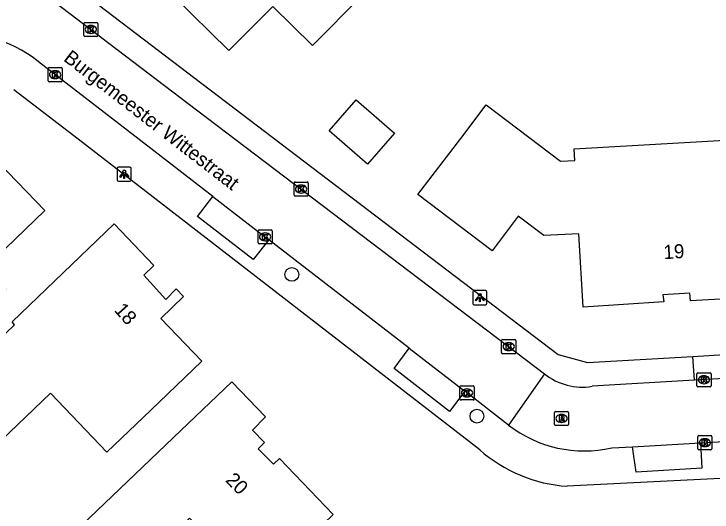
# Model space of a CAD drawing. Extents: x 159503 to 160347, y 382525 to 383272.
# Drawn here: x 159934.24 to 159983.69, y 382951.53 to 382986.8 of the extents above; entities that cross this region are included whole.
import ezdxf

# ---------------------------------------------------------------- set-up
doc = ezdxf.new("R2010")
doc.units = 0
for name, color, linetype in [('IMGEO_Boom', 7, 'Continuous'), ('IMGEO_Kolk', 7, 'Continuous'), ('IMGEO_Lichtpunt', 7, 'Continuous'), ('IMGEO_Openbare_ruimte_label', 7, 'Continuous'), ('IMGEO_Pand', 7, 'Continuous'), ('IMGEO_Pand_nummerreeks', 7, 'Continuous'), ('IMGEO_Rijbaan_lokaal_open', 7, 'Continuous'), ('IMGEO_Rioolput', 7, 'Continuous'), ('IMGEO_Voetpad_open', 7, 'Continuous')]:
    doc.layers.add(name, color=color, linetype=linetype)

msp = doc.modelspace()

# ---------------------------------------------------------------- linework, layer by layer
at = {"layer": 'IMGEO_Boom'}
for centre in [(159953.927, 382968.359), (159967.036, 382958.322)]:
    msp.add_circle(centre, 0.489, dxfattribs=at)
at = {"layer": 'IMGEO_Kolk'}
for p, q in [((159939.189, 382985.279), (159939.189, 382986.131)), ((159939.264, 382986.205), (159940.116, 382986.205)), ((159940.19, 382986.131), (159940.19, 382985.279)), ((159939.677, 382985.985), (159939.702, 382985.985)), ((159940.116, 382985.205), (159939.264, 382985.205)), ((159939.7, 382985.425), (159939.675, 382985.425)), ((159936.656, 382982.077), (159936.656, 382982.929)), ((159936.731, 382983.003), (159937.583, 382983.003)), ((159937.144, 382982.783), (159937.169, 382982.783)), ((159937.657, 382982.929), (159937.657, 382982.077)), ((159937.167, 382982.223), (159937.142, 382982.223)), ((159937.583, 382982.003), (159936.731, 382982.003)), ((159954.082, 382973.977), (159954.082, 382974.829)), ((159954.157, 382974.903), (159955.009, 382974.903)), ((159954.57, 382974.683), (159954.595, 382974.683)), ((159955.083, 382974.829), (159955.083, 382973.977)), ((159955.009, 382973.903), (159954.157, 382973.903)), ((159954.593, 382974.123), (159954.568, 382974.123)), ((159951.531, 382970.593), (159951.531, 382971.445)), ((159951.606, 382971.519), (159952.458, 382971.519)), ((159952.019, 382971.299), (159952.044, 382971.299)), ((159952.532, 382971.445), (159952.532, 382970.593)), ((159952.042, 382970.739), (159952.017, 382970.739)), ((159952.458, 382970.519), (159951.606, 382970.519)), ((159968.863, 382963.746), (159969.715, 382963.746)), ((159968.788, 382962.82), (159968.788, 382963.672)), ((159969.276, 382963.526), (159969.301, 382963.526)), ((159969.789, 382963.672), (159969.789, 382962.82)), ((159969.299, 382962.966), (159969.274, 382962.966)), ((159969.715, 382962.746), (159968.863, 382962.746)), ((159982.62, 382960.473), (159982.62, 382961.325)), ((159982.695, 382961.399), (159983.547, 382961.399)), ((159983.621, 382961.325), (159983.621, 382960.473)), ((159983.108, 382961.179), (159983.133, 382961.179)), ((159965.834, 382959.54), (159965.834, 382960.392)), ((159965.909, 382960.466), (159966.761, 382960.466)), ((159966.835, 382960.392), (159966.835, 382959.54)), ((159983.547, 382960.399), (159982.695, 382960.399)), ((159983.131, 382960.619), (159983.106, 382960.619)), ((159966.322, 382960.246), (159966.347, 382960.246)), ((159966.761, 382959.466), (159965.909, 382959.466)), ((159966.345, 382959.686), (159966.32, 382959.686)), ((159982.678, 382956.015), (159982.678, 382956.867)), ((159982.753, 382956.941), (159983.605, 382956.941)), ((159983.679, 382956.867), (159983.679, 382956.015)), ((159983.166, 382956.721), (159983.191, 382956.721)), ((159983.605, 382955.941), (159982.753, 382955.941)), ((159983.189, 382956.161), (159983.164, 382956.161))]:
    msp.add_line(p, q, dxfattribs=at)
for points in [[(159939.189, 382985.279), (159939.189, 382986.131)], [(159939.264, 382986.205), (159940.116, 382986.205)], [(159940.19, 382986.131), (159940.19, 382985.279)], [(159939.51, 382985.905), (159939.633, 382985.905), (159939.633, 382985.754), (159939.763, 382985.905), (159939.927, 382985.905), (159939.781, 382985.754), (159939.934, 382985.505), (159939.782, 382985.505), (159939.697, 382985.669), (159939.633, 382985.602), (159939.633, 382985.505), (159939.51, 382985.505), (159939.51, 382985.905)], [(159940.116, 382985.205), (159939.264, 382985.205)], [(159936.656, 382982.077), (159936.656, 382982.929)], [(159936.731, 382983.003), (159937.583, 382983.003)], [(159936.977, 382982.703), (159937.1, 382982.703), (159937.1, 382982.552), (159937.23, 382982.703), (159937.394, 382982.703), (159937.248, 382982.552), (159937.401, 382982.303), (159937.249, 382982.303), (159937.164, 382982.467), (159937.1, 382982.4), (159937.1, 382982.303), (159936.977, 382982.303), (159936.977, 382982.703)], [(159937.657, 382982.929), (159937.657, 382982.077)], [(159937.583, 382982.003), (159936.731, 382982.003)], [(159954.082, 382973.977), (159954.082, 382974.829)], [(159954.157, 382974.903), (159955.009, 382974.903)], [(159955.083, 382974.829), (159955.083, 382973.977)], [(159954.403, 382974.603), (159954.526, 382974.603), (159954.526, 382974.452), (159954.656, 382974.603), (159954.82, 382974.603), (159954.674, 382974.452), (159954.827, 382974.203), (159954.675, 382974.203), (159954.59, 382974.367), (159954.526, 382974.3), (159954.526, 382974.203), (159954.403, 382974.203), (159954.403, 382974.603)], [(159955.009, 382973.903), (159954.157, 382973.903)], [(159951.531, 382970.593), (159951.531, 382971.445)], [(159951.606, 382971.519), (159952.458, 382971.519)], [(159951.852, 382971.219), (159951.975, 382971.219), (159951.975, 382971.068), (159952.105, 382971.219), (159952.269, 382971.219), (159952.123, 382971.068), (159952.276, 382970.819), (159952.124, 382970.819), (159952.039, 382970.983), (159951.975, 382970.916), (159951.975, 382970.819), (159951.852, 382970.819), (159951.852, 382971.219)], [(159952.532, 382971.445), (159952.532, 382970.593)], [(159952.458, 382970.519), (159951.606, 382970.519)], [(159968.863, 382963.746), (159969.715, 382963.746)], [(159968.788, 382962.82), (159968.788, 382963.672)], [(159969.109, 382963.446), (159969.232, 382963.446), (159969.232, 382963.295), (159969.362, 382963.446), (159969.526, 382963.446), (159969.38, 382963.295), (159969.533, 382963.046), (159969.381, 382963.046), (159969.296, 382963.21), (159969.232, 382963.143), (159969.232, 382963.046), (159969.109, 382963.046), (159969.109, 382963.446)], [(159969.789, 382963.672), (159969.789, 382962.82)], [(159969.715, 382962.746), (159968.863, 382962.746)], [(159982.62, 382960.473), (159982.62, 382961.325)], [(159982.695, 382961.399), (159983.547, 382961.399)], [(159983.621, 382961.325), (159983.621, 382960.473)], [(159982.941, 382961.099), (159983.064, 382961.099), (159983.064, 382960.948), (159983.194, 382961.099), (159983.358, 382961.099), (159983.212, 382960.948), (159983.365, 382960.699), (159983.213, 382960.699), (159983.128, 382960.863), (159983.064, 382960.796), (159983.064, 382960.699), (159982.941, 382960.699), (159982.941, 382961.099)], [(159965.834, 382959.54), (159965.834, 382960.392)], [(159965.909, 382960.466), (159966.761, 382960.466)], [(159966.835, 382960.392), (159966.835, 382959.54)], [(159983.547, 382960.399), (159982.695, 382960.399)], [(159966.155, 382960.166), (159966.278, 382960.166), (159966.278, 382960.015), (159966.408, 382960.166), (159966.572, 382960.166), (159966.426, 382960.015), (159966.579, 382959.766), (159966.427, 382959.766), (159966.342, 382959.93), (159966.278, 382959.863), (159966.278, 382959.766), (159966.155, 382959.766), (159966.155, 382960.166)], [(159966.761, 382959.466), (159965.909, 382959.466)], [(159982.678, 382956.015), (159982.678, 382956.867)], [(159982.753, 382956.941), (159983.605, 382956.941)], [(159983.679, 382956.867), (159983.679, 382956.015)], [(159982.999, 382956.641), (159983.122, 382956.641), (159983.122, 382956.49), (159983.252, 382956.641), (159983.416, 382956.641), (159983.27, 382956.49), (159983.423, 382956.241), (159983.271, 382956.241), (159983.186, 382956.405), (159983.122, 382956.338), (159983.122, 382956.241), (159982.999, 382956.241), (159982.999, 382956.641)], [(159983.605, 382955.941), (159982.753, 382955.941)]]:
    msp.add_lwpolyline(points, dxfattribs=at)
for centre, start, end in [((159939.266, 382986.129), 91.552, 178.448), ((159939.266, 382986.129), 91.552, 178.448), ((159940.114, 382986.129), 1.552, 88.448), ((159940.114, 382986.129), 1.552, 88.448), ((159939.266, 382985.281), 181.552, 268.448), ((159939.266, 382985.281), 181.552, 268.448), ((159940.114, 382985.281), 271.552, 358.448), ((159940.114, 382985.281), 271.552, 358.448), ((159936.733, 382982.927), 91.552, 178.448), ((159936.733, 382982.927), 91.552, 178.448), ((159937.581, 382982.927), 1.552, 88.448), ((159937.581, 382982.927), 1.552, 88.448), ((159936.733, 382982.079), 181.552, 268.448), ((159936.733, 382982.079), 181.552, 268.448), ((159937.581, 382982.079), 271.552, 358.448), ((159937.581, 382982.079), 271.552, 358.448), ((159954.159, 382974.827), 91.552, 178.448), ((159954.159, 382974.827), 91.552, 178.448), ((159955.007, 382974.827), 1.552, 88.448), ((159955.007, 382974.827), 1.552, 88.448), ((159954.159, 382973.979), 181.552, 268.448), ((159954.159, 382973.979), 181.552, 268.448), ((159955.007, 382973.979), 271.552, 358.448), ((159955.007, 382973.979), 271.552, 358.448), ((159951.608, 382971.443), 91.552, 178.448), ((159951.608, 382971.443), 91.552, 178.448), ((159952.456, 382971.443), 1.552, 88.448), ((159952.456, 382971.443), 1.552, 88.448), ((159951.608, 382970.595), 181.552, 268.448), ((159951.608, 382970.595), 181.552, 268.448), ((159952.456, 382970.595), 271.552, 358.448), ((159952.456, 382970.595), 271.552, 358.448), ((159968.865, 382963.67), 91.552, 178.448), ((159968.865, 382963.67), 91.552, 178.448), ((159969.713, 382963.67), 1.552, 88.448), ((159969.713, 382963.67), 1.552, 88.448), ((159968.865, 382962.822), 181.552, 268.448), ((159968.865, 382962.822), 181.552, 268.448), ((159969.713, 382962.822), 271.552, 358.448), ((159969.713, 382962.822), 271.552, 358.448), ((159982.697, 382961.323), 91.552, 178.448), ((159982.697, 382961.323), 91.552, 178.448), ((159983.545, 382961.323), 1.552, 88.448), ((159983.545, 382961.323), 1.552, 88.448), ((159965.911, 382960.39), 91.552, 178.448), ((159965.911, 382960.39), 91.552, 178.448), ((159966.759, 382960.39), 1.552, 88.448), ((159966.759, 382960.39), 1.552, 88.448), ((159982.697, 382960.475), 181.552, 268.448), ((159982.697, 382960.475), 181.552, 268.448), ((159983.545, 382960.475), 271.552, 358.448), ((159983.545, 382960.475), 271.552, 358.448), ((159965.911, 382959.542), 181.552, 268.448), ((159965.911, 382959.542), 181.552, 268.448), ((159966.759, 382959.542), 271.552, 358.448), ((159966.759, 382959.542), 271.552, 358.448), ((159982.755, 382956.865), 91.552, 178.448), ((159982.755, 382956.865), 91.552, 178.448), ((159983.603, 382956.865), 1.552, 88.448), ((159983.603, 382956.865), 1.552, 88.448), ((159982.755, 382956.017), 181.552, 268.448), ((159982.755, 382956.017), 181.552, 268.448), ((159983.603, 382956.017), 271.552, 358.448), ((159983.603, 382956.017), 271.552, 358.448)]:
    msp.add_arc(centre, 0.0765, start, end, dxfattribs=at)
for centre, major_axis, ratio, start_param, end_param in [((159939.676, 382985.705), (-0.387, 0.002), 0.722429, 4.712389, 7.853982), ((159939.701, 382985.705), (-0.39, 0.002), 0.717154, 1.570796, 4.712389), ((159937.143, 382982.503), (-0.387, 0.002), 0.722429, 4.712389, 7.853982), ((159937.168, 382982.503), (-0.39, 0.002), 0.717154, 1.570796, 4.712389), ((159954.569, 382974.403), (-0.387, 0.002), 0.722429, 4.712389, 7.853982), ((159954.594, 382974.403), (-0.39, 0.002), 0.717154, 1.570796, 4.712389), ((159952.018, 382971.019), (-0.387, 0.002), 0.722429, 4.712389, 7.853982), ((159952.043, 382971.019), (-0.39, 0.002), 0.717154, 1.570796, 4.712389), ((159969.275, 382963.246), (-0.387, 0.002), 0.722429, 4.712389, 7.853982), ((159969.3, 382963.246), (-0.39, 0.002), 0.717154, 1.570796, 4.712389), ((159983.107, 382960.899), (-0.387, 0.002), 0.722429, 4.712389, 7.853982), ((159983.132, 382960.899), (-0.39, 0.002), 0.717154, 1.570796, 4.712389), ((159966.321, 382959.966), (-0.387, 0.002), 0.722429, 4.712389, 7.853982), ((159966.346, 382959.966), (-0.39, 0.002), 0.717154, 1.570796, 4.712389), ((159983.165, 382956.441), (-0.387, 0.002), 0.722429, 4.712389, 7.853982), ((159983.19, 382956.441), (-0.39, 0.002), 0.717154, 1.570796, 4.712389)]:
    msp.add_ellipse(centre, major_axis=major_axis, ratio=ratio, start_param=start_param, end_param=end_param, dxfattribs=at)
at = {"layer": 'IMGEO_Lichtpunt'}
for p, q in [((159941.56, 382975.859), (159941.56, 382975.052)), ((159941.56, 382975.859), (159941.56, 382975.052)), ((159942.462, 382975.954), (159941.654, 382975.954)), ((159942.462, 382975.954), (159941.654, 382975.954)), ((159942.556, 382975.052), (159942.556, 382975.859)), ((159942.556, 382975.052), (159942.556, 382975.859)), ((159941.654, 382974.958), (159942.462, 382974.958)), ((159941.654, 382974.958), (159942.462, 382974.958)), ((159967.644, 382967.21), (159966.836, 382967.21)), ((159967.644, 382967.21), (159966.836, 382967.21)), ((159966.742, 382967.115), (159966.742, 382966.308)), ((159966.742, 382967.115), (159966.742, 382966.308)), ((159967.738, 382966.308), (159967.738, 382967.115)), ((159967.738, 382966.308), (159967.738, 382967.115)), ((159966.836, 382966.214), (159967.644, 382966.214)), ((159966.836, 382966.214), (159967.644, 382966.214))]:
    msp.add_line(p, q, dxfattribs=at)
for points in [[(159941.934, 382975.523), (159941.973, 382975.495), (159941.785, 382975.233), (159941.747, 382975.26), (159941.934, 382975.523)], [(159942.036, 382975.475), (159942.083, 382975.475), (159942.083, 382975.153), (159942.036, 382975.153), (159942.036, 382975.475)], [(159942.146, 382975.495), (159942.184, 382975.522), (159942.371, 382975.26), (159942.332, 382975.232), (159942.146, 382975.495)], [(159967.116, 382966.779), (159967.155, 382966.751), (159966.967, 382966.489), (159966.929, 382966.516), (159967.116, 382966.779)], [(159967.218, 382966.731), (159967.265, 382966.731), (159967.265, 382966.409), (159967.218, 382966.409), (159967.218, 382966.731)], [(159967.328, 382966.751), (159967.366, 382966.778), (159967.553, 382966.516), (159967.514, 382966.488), (159967.328, 382966.751)]]:
    msp.add_lwpolyline(points, dxfattribs=at)
for centre in [(159942.059, 382975.657), (159967.241, 382966.913)]:
    msp.add_circle(centre, 0.0994, dxfattribs=at)
for centre, start, end in [((159941.654, 382975.859), 90, 180), ((159941.654, 382975.859), 90, 180), ((159942.462, 382975.859), 0, 90), ((159942.462, 382975.859), 0, 90), ((159941.654, 382975.052), 180, 270), ((159941.654, 382975.052), 180, 270), ((159942.462, 382975.052), 270, 0), ((159942.462, 382975.052), 270, 360), ((159966.836, 382967.115), 90, 180), ((159966.836, 382967.115), 90, 180), ((159967.644, 382967.115), 0, 90), ((159967.644, 382967.115), 0, 90), ((159966.836, 382966.308), 180, 270), ((159966.836, 382966.308), 180, 270), ((159967.644, 382966.308), 270, 0), ((159967.644, 382966.308), 270, 360)]:
    msp.add_arc(centre, 0.0946, start, end, dxfattribs=at)
at = {"layer": 'IMGEO_Pand'}
for points in [[(159961.16, 382990.415), (159958.888, 382988.116), (159955.382, 382984.566), (159952.57, 382987.322), (159949.454, 382984.218), (159941.58, 382991.973), (159947.894, 382998.384), (159951.029, 382995.297), (159953.143, 382993.216), (159955.69, 382995.802), (159959.253, 382992.294), (159961.16, 382990.415)], [(159961.208, 382978.373), (159959.289, 382976.161), (159956.574, 382978.516), (159958.493, 382980.728), (159961.208, 382978.373)], [(159987.908, 382978.054), (159988.265, 382971.829), (159988.551, 382966.837), (159982.16, 382966.482), (159982.117, 382967.02), (159980.216, 382966.903), (159980.265, 382966.415), (159974.571, 382966.048), (159974.248, 382971.235), (159971.787, 382971.11), (159969.948, 382972.492), (159968.113, 382970.035), (159962.862, 382974.012), (159965.887, 382977.994), (159967.689, 382980.367), (159972.945, 382976.375), (159973.964, 382976.433), (159973.916, 382977.252), (159987.908, 382978.054)], [(159916.211, 382960.394), (159919.327, 382963.349), (159920.208, 382962.421), (159923.869, 382965.893), (159920.764, 382969.094), (159920.247, 382968.592), (159917.253, 382971.679), (159918.389, 382972.78), (159914.883, 382976.395), (159916.389, 382977.855), (159919.894, 382974.24), (159923.132, 382977.38), (159924.656, 382975.807), (159925.603, 382976.725), (159926.856, 382975.432), (159930.517, 382978.982), (159936.424, 382972.89), (159932.235, 382968.858), (159933.664, 382967.34), (159930.234, 382964.041)], [(159930.234, 382964.041), (159931.771, 382962.416), (159934.286, 382964.793), (159934.106, 382964.998), (159941.347, 382971.931), (159944.155, 382968.989), (159943.448, 382968.307), (159944.994, 382966.583), (159945.743, 382967.327), (159946.261, 382966.792), (159944.645, 382965.232), (159947.554, 382962.207), (159943.937, 382958.756), (159940.81, 382955.771), (159936.827, 382959.946), (159932.161, 382955.493), (159926.984, 382960.92)], [(159942.81, 382945.14), (159941.604, 382946.347), (159935.384, 382940.398), (159932.01, 382943.902), (159946.063, 382957.311), (159949.681, 382960.761), (159952.057, 382958.267), (159951.15, 382957.329), (159951.983, 382956.452), (159951.534, 382956.005), (159952.617, 382954.913), (159953.046, 382955.323), (159956.844, 382951.362), (159953.255, 382947.882), (159951.397, 382946.081), (159946.683, 382951.101), (159944.62, 382949.165), (159945.781, 382947.93), (159942.81, 382945.14)]]:
    msp.add_lwpolyline(points, dxfattribs=at)
at = {"layer": 'IMGEO_Rijbaan_lokaal_open'}
for points in [[(159936.514, 382988.127), (159946.588, 382980.466), (159971.819, 382961.325)], [(159948.338, 382973.876), (159943.932, 382977.28), (159935.974, 382983.418)], [(159967.231, 382955.939), (159938.787, 382977.935), (159934.243, 382981.423)], [(159952.293, 382970.819), (159951.192, 382969.404), (159947.245, 382972.454), (159948.338, 382973.876)], [(159948.338, 382973.876), (159952.293, 382970.819)], [(159962.244, 382963.13), (159952.293, 382970.819)], [(159966.186, 382960.084), (159965.084, 382958.658), (159961.175, 382961.695), (159962.244, 382963.13)], [(159962.244, 382963.13), (159966.186, 382960.084)], [(159971.819, 382961.325), (159969.281, 382957.692)], [(159992.466, 382961.44), (159989.696, 382961.282), (159982.453, 382960.859)], [(159982.453, 382960.859), (159975.211, 382960.437)], [(159969.281, 382957.692), (159966.186, 382960.084)], [(159982.87, 382956.422), (159992.548, 382956.964)], [(159978.059, 382956.156), (159982.87, 382956.422)], [(159982.87, 382956.422), (159982.969, 382954.641), (159978.306, 382954.358), (159978.059, 382956.156)], [(159976.584, 382956.075), (159978.059, 382956.156)], [(160000.149, 382954.763), (159999.933, 382954.745), (159991.369, 382954.262), (159973.432, 382953.353)]]:
    msp.add_lwpolyline(points, dxfattribs=at)
for centre, radius, start, end in [((159930.645, 382976.933), 8.394, 50.5908, 102.6717), ((159974.502, 382964.651), 4.273, 231.1078, 279.5514), ((159974.645, 382964.619), 8.761, 232.245, 282.7855), ((159974.163, 382963.833), 10.506, 228.7136, 266.0112)]:
    msp.add_arc(centre, radius, start, end, dxfattribs=at)
at = {"layer": 'IMGEO_Rioolput'}
for p, q in [((159972.531, 382957.733), (159972.531, 382958.585)), ((159972.606, 382958.659), (159973.458, 382958.659)), ((159973.019, 382958.439), (159973.044, 382958.439)), ((159973.532, 382958.585), (159973.532, 382957.733)), ((159973.042, 382957.879), (159973.017, 382957.879)), ((159973.458, 382957.659), (159972.606, 382957.659))]:
    msp.add_line(p, q, dxfattribs=at)
for points in [[(159972.531, 382957.733), (159972.531, 382958.585)], [(159972.606, 382958.659), (159973.458, 382958.659)], [(159973.12, 382958.357), (159972.868, 382958.359), (159972.868, 382957.959)], [(159973.532, 382958.585), (159973.532, 382957.733)], [(159972.868, 382957.959), (159972.992, 382957.959), (159972.992, 382958.121), (159973.003, 382958.121)], [(159973.046, 382958.278), (159972.992, 382958.278), (159972.992, 382958.197)], [(159972.992, 382958.197), (159973.044, 382958.197)], [(159973.05, 382958.092), (159973.121, 382957.959), (159973.261, 382957.959), (159973.196, 382958.085)], [(159973.458, 382957.659), (159972.606, 382957.659)]]:
    msp.add_lwpolyline(points, dxfattribs=at)
for centre, radius, start, end in [((159972.608, 382958.583), 0.0765, 91.552, 178.448), ((159972.608, 382958.583), 0.0765, 91.552, 178.448), ((159973.119, 382958.247), 0.109, 350.3612, 89.416), ((159973.456, 382958.583), 0.0765, 1.552, 88.448), ((159973.456, 382958.583), 0.0765, 1.552, 88.448), ((159973.002, 382958.068), 0.0533, 26.0293, 88.6989), ((159973.028, 382958.386), 0.19, 274.7715, 282.9687), ((159973.052, 382958.182), 0.0964, 77.0061, 93.1865), ((159973.066, 382958.239), 0.0378, 276.6634, 79.6772), ((159973.117, 382958.247), 0.112, 277.5842, 350.9817), ((159973.101, 382958.032), 0.108, 29.5134, 73.7905), ((159972.608, 382957.735), 0.0765, 181.552, 268.448), ((159972.608, 382957.735), 0.0765, 181.552, 268.448), ((159973.456, 382957.735), 0.0765, 271.552, 358.448), ((159973.456, 382957.735), 0.0765, 271.552, 358.448)]:
    msp.add_arc(centre, radius, start, end, dxfattribs=at)
for centre, major_axis, ratio, start_param, end_param in [((159973.018, 382958.159), (-0.387, 0.002), 0.722429, 4.712389, 7.853982), ((159973.043, 382958.159), (-0.39, 0.002), 0.717154, 1.570796, 4.712389)]:
    msp.add_ellipse(centre, major_axis=major_axis, ratio=ratio, start_param=start_param, end_param=end_param, dxfattribs=at)
at = {"layer": 'IMGEO_Voetpad_open'}
for points in [[(159982.324, 382962.546), (159992.571, 382963.192), (159994.756, 382964.255), (160000, 382970.621), (160005.936, 382977.853), (160024.041, 383000), (160036.566, 383015.316)], [(159937.661, 382989.432), (159947.551, 382981.884), (159972.788, 382962.692), (159974.862, 382962.113), (159982.324, 382962.546)], [(159982.453, 382960.859), (159982.324, 382962.546)]]:
    msp.add_lwpolyline(points, dxfattribs=at)

# ---------------------------------------------------------------- texts
at = {"layer": 'IMGEO_Openbare_ruimte_label'}
msp.add_text('Burgemeester Wittestraat', height=1, rotation=322.3161, dxfattribs=at).set_placement((159937.694, 382983.535))
at = {"layer": 'IMGEO_Pand_nummerreeks'}
for s, rotation, p in [('19', 3.5219, (159980.277, 382969.432)), ('18', 311.8842, (159941.29, 382965.801)), ('20', 314.7629, (159949.167, 382953.734))]:
    msp.add_text(s, height=1, rotation=rotation, dxfattribs=at).set_placement(p)

doc.saveas('drawing.dxf')
